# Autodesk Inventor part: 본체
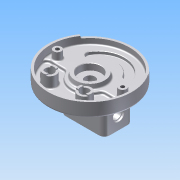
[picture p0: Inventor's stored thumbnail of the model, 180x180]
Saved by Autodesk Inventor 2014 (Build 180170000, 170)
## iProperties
Company: 한국ATC센터
Created: 2015-04
Part Number: 본체
Document SubType Name: Modeling
Designer: KYOUNG IL JANG
Density: 2.71 g/cm^3
Material: 알루미늄-6061
Mass: 1340.83 g
Surface Area: 1387.38 cm^2
Volume: 494.771 cm^3
Appearance: 매끄러움 - 흰색
Author: KYOUNG IL JANG
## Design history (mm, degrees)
sketch "스케치1"
  geometry: L1 (-59, -19)-(-59, 19); L2 (59, 19)-(59, -19); L3 (-41, 19)-(-41, -19); L4 (41, -19)-(41, 19); L5 (38.527, 33.023)-(55.442, 39.179); L6 (-38.527, 33.023)-(-55.442, 39.179); C1 r 90 at (0, 0); C2 r 95 at (0, 0); A1 r 59 centre (0, 19) between (59, 19) and (-59, 19); A2 r 59 centre (0, -19) between (-59, -19) and (59, -19); A3 r 41 centre (0, -19) between (-41, -19) and (41, -19); A4 r 41 centre (0, 19) between (41, 19) and (-41, 19); 2 further points
  constraints: 12 end point, 12 point on circle, 6 centre point, 4 tangent, 2 parallel, 2 point on line, 1 coincident, 1 horizontal alignment, 1 midpoint, 1 vertical, 1 vertical alignment, 3 other
  dimensions: "d2" = 180 diameter of C1; "d3" = 156 dimension on A2 A1; "d4" = 118 distance between parallel lines of L2 L1; "d5" = 18 distance between parallel lines of L2 L4; "d8" = 190 diameter of C2; "d124" = 110 deg dimension on A1.centre point (0, 0) L5.end; "d125" = 140 deg angle of L5 L6
extrude "돌출1" new body sketch "스케치1" distance "d6" = 14; taper "d7" = 0 deg
extrude "돌출2" join sketch "스케치1" distance "d9" = 13; taper "d10" = 0 deg
extrude "돌출3" cut sketch "스케치1" distance "d11" = 7; taper "d12" = 0 deg
sketch "스케치2"
  geometry: C1 r 11.5 at (0, 0); 1 further point
  constraints: 1 centre point, 1 coincident
  dimensions: "d13" = 23 diameter of C1
extrude "돌출4" cut sketch "스케치2" stored distance "d14" = 7; taper "d15" = 0 deg
fillet "모깎기1"
fillet "모깎기2"
sketch "스케치3"
  geometry: L1 (-73.724, 51.622)-(-77.819, 54.49); L2 (73.724, 51.622)-(77.819, 54.49); L3 (0, 0)-(0, -90); A1 r 95 centre (0, 0) between (-77.819, 54.49) and (77.819, 54.49) reference; A2 r 90 centre (0, 0) between (-73.724, 51.622) and (73.724, 51.622) reference; 1 further point
  constraints: 6 end point, 5 point on circle, 1 point on line, 1 vertical, 1 other
  dimensions: "d16" = 250 deg dimension on L2 L1
extrude "돌출5" join sketch "스케치3" distance "d17" = 5; taper "d18" = 0 deg
hole "구멍1" diameter "d21" = 50; stored, may be unused: countersink angle "d25" = 90 deg, drill point angle "d27" = 0 deg; dims "d19" = 10, "d20" = 10, "d22" = 6, "d23" = 4, "d24" = 2, "d26" = 5
fillet "모깎기3" dims "d28" = 0.3
fillet "모깎기5" dims "d30" = 3
sketch "스케치4"
  geometry: C1 r 35 at (0, 0); C2 r 25 at (0, 0); 1 further point
  constraints: 2 centre point, 1 coincident
  dimensions: "d32" = 70 diameter of C1 (derived); "d36" = 10 radial gap between concentric circles of C1 C2
extrude "돌출6" join sketch "스케치4" distance "d33" = 10; taper "d34" = 0 deg
feature "면 기울기2" dims angle "d37" = 10 deg
chamfer "모따기1" distance "d39" = 1; stored, may be unused: second distance "d40" = 2, angle "d41" = 45 deg
fillet "모깎기7" dims "d42" = 5
sketch "스케치5"
  geometry: L1 (-40.249, -12)-(-89.196, -12); L2 (40.249, -12)-(89.196, -12); A1 r 90 centre (0, 0) between (-89.196, -12) and (89.196, -12) reference; A2 r 42 centre (0, 0) between (-40.249, -12) and (40.249, -12); 1 further point
  constraints: 4 end point, 4 point on circle, 1 centre point, 1 collinear, 1 horizontal, 1 point on line
  dimensions: "d43" = 48 radial gap between concentric circles of A1 A2; "d44" = 12 distance from line of point (0, 0) L1
extrude "돌출7" cut sketch "스케치5" stored distance "d45" = 10; taper "d46" = 0 deg
fillet "모깎기8" dims "d47" = 10
chamfer "모따기2" distance "d49" = 1; stored, may be unused: second distance "d50" = 2, angle "d51" = 45 deg
sketch "스케치8"
  geometry: C1 r 9 at (74, 0); C2 r 9 at (-74, 0); A1 r 74 centre (0, 0) between (74, 0) and (-74, 0); 1 further point
  constraints: 3 centre point, 2 horizontal alignment, 2 point on circle, 1 coincident, 1 equal radius
  dimensions: "d64" = 18 diameter of C1; "d65" = 148 diameter of A1
extrude "돌출9" join sketch "스케치8" stored distance "d66" = 5; taper "d67" = 0 deg
sketch "스케치11"
  geometry: C1 r 15 at (40, -52); C2 r 15 at (-40, -52); 1 further point
  constraints: 2 centre point, 1 equal radius, 1 horizontal alignment
  dimensions: "d82" = 52 vertical distance of point (0, 0) C1.centre; "d83" = 30 diameter of C1; "d84" = 80 distance of C2.centre C1.centre; "d85" = 40 horizontal distance of point (0, 0) C1.centre (= 0.5 x d84)
extrude "돌출10" join sketch "스케치11" stored distance "d86" = 10; taper "d87" = 0 deg
node "구멍3"
node "구멍5"
hole "구멍6" diameter "d92" = 20; stored, may be unused: countersink angle "d96" = 90 deg, drill point angle "d98" = 118 deg; dims "d90" = 10, "d91" = 10, "d93" = 6, "d94" = 4, "d95" = 2, "d97" = 8
hole "구멍7" diameter "d101" = 20; stored, may be unused: countersink angle "d105" = 90 deg, drill point angle "d107" = 118 deg; dims "d99" = 10, "d100" = 10, "d102" = 6, "d103" = 4, "d104" = 2, "d106" = 8
fillet "모깎기13" dims "d108" = 3
sketch "스케치13"
  geometry: L1 (-20.252, -58)-(-26, -58); L2 (-42, -58)-(-47.748, -58); L3 (-20.252, -46)-(-26, -46); L4 (-42, -46)-(-47.748, -46); L5 (-108, -65.748)-(-108, -60); L6 (-108, -44)-(-108, -38.252); L7 (-120, -44)-(-120, -38.252); L8 (-120, -60)-(-120, -65.748); A1 r 15 centre (-34, -52) between (-20.252, -58) and (-47.748, -58) reference; A2 r 10 centre (-34, -52) between (-26, -58) and (-42, -58) reference; A3 r 15 centre (-114, -52) between (-108, -65.748) and (-108, -38.252) reference; A4 r 10 centre (-114, -52) between (-108, -60) and (-108, -44) reference; 1 further point
  constraints: 16 end point, 16 point on circle, 3 equal length, 3 point on line, 2 collinear, 1 horizontal, 1 perpendicular
  dimensions: "d114" = 12 distance between parallel lines of L4 L2; "d115" = 6 distance from line of A1.centre L2 (= 0.5 x d114); "d116" = 12 distance between parallel lines of L8 L5 (= d114); "d117" = 6 distance from line of A3.centre L5 (= d115)
extrude "돌출12" join sketch "스케치13" distance "d118" = 3; taper "d119" = 0 deg
fillet "모깎기14" dims "d120" = 1
sketch "스케치14"
  geometry: L1 (23, 32.5)-(-53, 32.5); L2 (-65, 20.5)-(-65, -20.5); L3 (-53, -32.5)-(23, -32.5); L4 (35, -20.5)-(35, 20.5); L5 (30, 20.5)-(30, -20.5); L6 (23, -27.5)-(-53, -27.5); L7 (-60, -20.5)-(-60, 20.5); L8 (-53, 27.5)-(23, 27.5); A1 r 12 centre (-53, -20.5) between (-65, -20.5) and (-53, -32.5); A2 r 12 centre (-53, 20.5) between (-53, 32.5) and (-65, 20.5); A3 r 12 centre (23, 20.5) between (35, 20.5) and (23, 32.5); A4 r 12 centre (23, -20.5) between (23, -32.5) and (35, -20.5); A5 r 7 centre (23, -20.5) between (23, -27.5) and (30, -20.5); A6 r 7 centre (-53, -20.5) between (-60, -20.5) and (-53, -27.5); A7 r 7 centre (-53, 20.5) between (-53, 27.5) and (-60, 20.5); A8 r 7 centre (23, 20.5) between (30, 20.5) and (23, 27.5); A9 r 6 centre (-23, -25) between (-17.546, -27.5) and (-28.454, -27.5); A10 r 6 centre (-23, 25) between (-28.454, 27.5) and (-17.546, 27.5); 6 further points
  constraints: 20 point on circle, 16 end point, 12 point on line, 10 centre point, 8 tangent, 4 equal radius, 4 parallel, 2 perpendicular, 1 horizontal, 1 horizontal alignment, 1 midpoint, 1 vertical alignment, 7 other
  dimensions: "d126" = 35 distance from line of point (0, 0) L4; "d127" = 65 distance of point (35, -32.5) point (35, 32.5); "d128" = 100 distance of point (35, 32.5) point (-65, 32.5); "d132" = 12 radius of A1; "d133" = 5 distance between parallel lines of L5 L4; "d141" = 42 distance from line of A9.centre L2; "d142" = 12 diameter of A9; "d143" = 50 distance of A10.centre A9.centre; "d144" = 25 vertical distance of point (0, 0) A9.centre (= 0.5 x d143)
extrude "돌출13" join sketch "스케치14" distance "d130" = 58; taper "d131" = 0 deg
fillet "모깎기16" dims "d145" = 3
hole "구멍8" diameter "d148" = 4.134; stored, may be unused: countersink angle "d152" = 90 deg, drill point angle "d154" = 118 deg; dims "d146" = 10, "d147" = 10, "d149" = 12, "d150" = 4, "d151" = 2, "d153" = 15
hole "구멍9" diameter "d157" = 4.134; stored, may be unused: countersink angle "d161" = 90 deg, drill point angle "d163" = 118 deg; dims "d155" = 10, "d156" = 10, "d158" = 12, "d159" = 4, "d160" = 2, "d162" = 15
sketch "스케치17"
  geometry: L1 (-58, 110.5)-(-58, -69.5) reference; C1 r 15 at (-29.5, 20.5); 1 further point
  constraints: 1 centre point, 1 horizontal alignment
  dimensions: "d164" = 28.5 distance from line of C1.centre L1; "d165" = 30 diameter of C1
extrude "돌출16" join sketch "스케치17" distance "d166" = 28; taper "d167" = 0 deg
fillet "모깎기17" dims "d168" = 1
hole "구멍10" diameter "d171" = 22; stored, may be unused: countersink angle "d175" = 90 deg, drill point angle "d177" = 118 deg; dims "d169" = 10, "d170" = 10, "d172" = 12, "d173" = 26, "d174" = 4, "d176" = 15
node "솔리드1"
sketch "스케치9"
  geometry: 1 further point
hole "구멍2" sketch "스케치9" diameter "d68" = 8.376; stored, may be unused: countersink angle "d72" = 90 deg, drill point angle "d74" = 120 deg; dims "d69" = 16, "d70" = 4, "d71" = 2, "d73" = 21
sketch "스케치10"
  geometry: 1 further point
hole "구멍4" sketch "스케치10" diameter "d75" = 8.376; stored, may be unused: countersink angle "d79" = 90 deg, drill point angle "d81" = 120 deg; dims "d76" = 16, "d77" = 4, "d78" = 2, "d80" = 21
